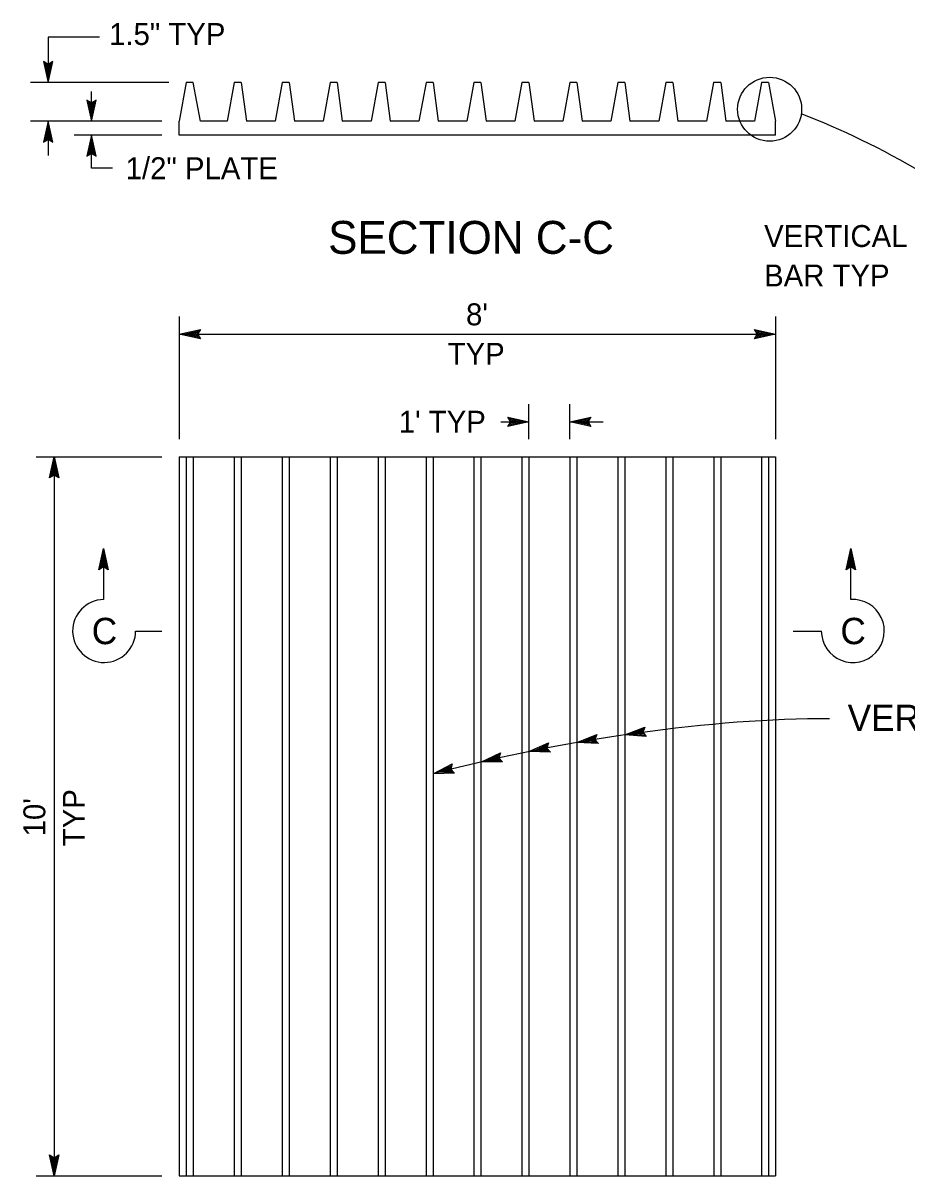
# Model space of a CAD drawing. Extents: x 6709491 to 6710959, y 1869789 to 1870763.
# Drawn here: x 6710131.7 to 6710373.6, y 1870447.9 to 1870763.4 of the extents above; entities that cross this region are included whole.
import ezdxf

# ---------------------------------------------------------------- set-up
doc = ezdxf.new("R2010")
doc.units = 0
for name, color, linetype in [('56 Stg 3 Anno', 7, 'Continuous'), ('57 Undefined', 7, 'Continuous'), ('60 Nongeo Data', 7, 'Continuous')]:
    doc.layers.add(name, color=color, linetype=linetype)

msp = doc.modelspace()

# ---------------------------------------------------------------- linework, layer by layer
at = {"layer": '56 Stg 3 Anno'}
for p, q in [((6710152.62, 1870759.57), (6710138.55, 1870759.57)), ((6710138.55, 1870759.57), (6710138.55, 1870747.15)), ((6710138.55, 1870752.14), (6710137.26, 1870752.91)), ((6710137.26, 1870752.91), (6710137.26, 1870752.91)), ((6710137.26, 1870752.91), (6710138.55, 1870747.15)), ((6710137.6, 1870752.7), (6710138.55, 1870748.47)), ((6710137.95, 1870752.47), (6710138.55, 1870749.8)), ((6710138.28, 1870752.31), (6710138.55, 1870751.13)), ((6710138.55, 1870747.15), (6710139.83, 1870752.91)), ((6710139.83, 1870752.91), (6710138.55, 1870752.14)), ((6710138.55, 1870748.48), (6710139.48, 1870752.68)), ((6710138.55, 1870749.8), (6710139.15, 1870752.51)), ((6710138.55, 1870751.13), (6710138.8, 1870752.29)), ((6710139.83, 1870752.91), (6710139.83, 1870752.91)), ((6710171.55, 1870747.15), (6710133.75, 1870747.15)), ((6710138.55, 1870747.15), (6710138.55, 1870747.15)), ((6710150.43, 1870736.59), (6710150.43, 1870744.71)), ((6710150.43, 1870741.58), (6710149.14, 1870742.35)), ((6710149.14, 1870742.35), (6710149.14, 1870742.35)), ((6710149.14, 1870742.35), (6710150.43, 1870736.59)), ((6710149.48, 1870742.14), (6710150.43, 1870737.91)), ((6710149.83, 1870741.91), (6710150.43, 1870739.24)), ((6710150.16, 1870741.75), (6710150.43, 1870740.57)), ((6710150.43, 1870736.59), (6710151.71, 1870742.35)), ((6710151.71, 1870742.35), (6710150.43, 1870741.58)), ((6710150.43, 1870737.92), (6710151.36, 1870742.12)), ((6710150.43, 1870739.24), (6710151.03, 1870741.95)), ((6710150.43, 1870740.57), (6710150.68, 1870741.73)), ((6710151.71, 1870742.35), (6710151.71, 1870742.35)), ((6710169.63, 1870736.59), (6710133.75, 1870736.59)), ((6710138.55, 1870736.59), (6710137.27, 1870730.83)), ((6710138.55, 1870735.25), (6710137.62, 1870731.05)), ((6710138.55, 1870736.59), (6710138.55, 1870727.21)), ((6710139.84, 1870730.83), (6710138.55, 1870736.59)), ((6710138.55, 1870736.59), (6710138.55, 1870736.59)), ((6710139.49, 1870731.03), (6710138.55, 1870735.26)), ((6710150.43, 1870736.59), (6710150.43, 1870736.59)), ((6710138.55, 1870733.93), (6710137.95, 1870731.22)), ((6710138.55, 1870732.61), (6710138.3, 1870731.45)), ((6710139.15, 1870731.26), (6710138.55, 1870733.93)), ((6710138.82, 1870731.43), (6710138.55, 1870732.61)), ((6710169.63, 1870732.75), (6710145.63, 1870732.75)), ((6710150.43, 1870732.75), (6710149.15, 1870726.99)), ((6710150.43, 1870723.72), (6710150.43, 1870732.75)), ((6710151.72, 1870726.99), (6710150.43, 1870732.75)), ((6710150.43, 1870732.75), (6710150.43, 1870732.75)), ((6710137.27, 1870730.83), (6710138.55, 1870731.59)), ((6710137.27, 1870730.83), (6710137.27, 1870730.83)), ((6710138.55, 1870731.59), (6710139.84, 1870730.83)), ((6710139.84, 1870730.83), (6710139.84, 1870730.83)), ((6710150.43, 1870731.41), (6710149.5, 1870727.21)), ((6710150.43, 1870730.09), (6710149.83, 1870727.38)), ((6710150.43, 1870728.77), (6710150.18, 1870727.61)), ((6710151.37, 1870727.19), (6710150.43, 1870731.42)), ((6710151.03, 1870727.42), (6710150.43, 1870730.09)), ((6710150.7, 1870727.59), (6710150.43, 1870728.77)), ((6710149.15, 1870726.99), (6710150.43, 1870727.75)), ((6710149.15, 1870726.99), (6710149.15, 1870726.99)), ((6710150.43, 1870727.75), (6710151.72, 1870726.99)), ((6710151.72, 1870726.99), (6710151.72, 1870726.99)), ((6710156.16, 1870723.72), (6710150.43, 1870723.72)), ((6710174.43, 1870683.13), (6710174.43, 1870649.53)), ((6710337.63, 1870683.13), (6710337.63, 1870649.53)), ((6710174.43, 1870678.33), (6710180.19, 1870679.61)), ((6710174.43, 1870678.33), (6710180.19, 1870679.61)), ((6710174.43, 1870678.33), (6710337.63, 1870678.33)), ((6710180.19, 1870677.04), (6710174.43, 1870678.33)), ((6710174.43, 1870678.33), (6710174.43, 1870678.33)), ((6710180.19, 1870677.04), (6710174.43, 1870678.33)), ((6710174.43, 1870678.33), (6710174.43, 1870678.33)), ((6710179.98, 1870677.39), (6710175.75, 1870678.33)), ((6710179.98, 1870677.39), (6710175.75, 1870678.33)), ((6710175.77, 1870678.33), (6710179.96, 1870679.26)), ((6710175.77, 1870678.33), (6710179.96, 1870679.26)), ((6710177.08, 1870678.33), (6710179.79, 1870678.93)), ((6710177.08, 1870678.33), (6710179.79, 1870678.93)), ((6710179.76, 1870677.73), (6710177.08, 1870678.33)), ((6710179.76, 1870677.73), (6710177.08, 1870678.33)), ((6710178.41, 1870678.33), (6710179.57, 1870678.59)), ((6710178.41, 1870678.33), (6710179.57, 1870678.59)), ((6710179.59, 1870678.06), (6710178.41, 1870678.33)), ((6710179.59, 1870678.06), (6710178.41, 1870678.33)), ((6710180.19, 1870679.61), (6710179.42, 1870678.33)), ((6710180.19, 1870679.61), (6710179.42, 1870678.33)), ((6710179.42, 1870678.33), (6710180.19, 1870677.04)), ((6710179.42, 1870678.33), (6710180.19, 1870677.04)), ((6710180.19, 1870679.61), (6710180.19, 1870679.61)), ((6710180.19, 1870679.61), (6710180.19, 1870679.61)), ((6710332.64, 1870678.33), (6710331.87, 1870679.62)), ((6710331.87, 1870679.62), (6710331.87, 1870679.62)), ((6710331.87, 1870679.62), (6710337.63, 1870678.33)), ((6710337.63, 1870678.33), (6710331.87, 1870677.05)), ((6710331.87, 1870677.05), (6710332.64, 1870678.33)), ((6710332.08, 1870679.28), (6710336.31, 1870678.33)), ((6710336.3, 1870678.33), (6710332.1, 1870677.4)), ((6710334.98, 1870678.33), (6710332.27, 1870677.73)), ((6710332.31, 1870678.93), (6710334.98, 1870678.33)), ((6710332.48, 1870678.6), (6710333.66, 1870678.33)), ((6710333.66, 1870678.33), (6710332.49, 1870678.08)), ((6710337.63, 1870678.33), (6710337.63, 1870678.33)), ((6710180.19, 1870677.04), (6710180.19, 1870677.04)), ((6710180.19, 1870677.04), (6710180.19, 1870677.04)), ((6710331.87, 1870677.05), (6710331.87, 1870677.05)), ((6710270.11, 1870649.53), (6710270.11, 1870659.14)), ((6710281.31, 1870649.53), (6710281.31, 1870659.14)), ((6710262.46, 1870654.34), (6710270.11, 1870654.34)), ((6710265.12, 1870654.34), (6710264.35, 1870655.62)), ((6710264.35, 1870655.62), (6710264.35, 1870655.62)), ((6710264.35, 1870655.62), (6710270.11, 1870654.34)), ((6710270.11, 1870654.34), (6710264.35, 1870653.06)), ((6710264.35, 1870653.06), (6710265.12, 1870654.34)), ((6710264.35, 1870653.06), (6710264.35, 1870653.06)), ((6710264.56, 1870655.28), (6710268.79, 1870654.34)), ((6710268.78, 1870654.33), (6710264.58, 1870653.41)), ((6710267.46, 1870654.34), (6710264.75, 1870653.74)), ((6710264.79, 1870654.94), (6710267.46, 1870654.34)), ((6710264.96, 1870654.6), (6710266.14, 1870654.34)), ((6710266.14, 1870654.34), (6710264.98, 1870654.08)), ((6710270.11, 1870654.34), (6710270.11, 1870654.34)), ((6710281.31, 1870654.34), (6710287.08, 1870655.62)), ((6710281.31, 1870654.34), (6710290.43, 1870654.34)), ((6710287.08, 1870653.05), (6710281.31, 1870654.34)), ((6710281.31, 1870654.34), (6710281.31, 1870654.34)), ((6710286.87, 1870653.39), (6710282.64, 1870654.34)), ((6710282.65, 1870654.34), (6710286.85, 1870655.27)), ((6710283.97, 1870654.34), (6710286.68, 1870654.94)), ((6710286.64, 1870653.74), (6710283.97, 1870654.34)), ((6710285.29, 1870654.34), (6710286.45, 1870654.59)), ((6710286.47, 1870654.07), (6710285.29, 1870654.34)), ((6710287.08, 1870655.62), (6710286.31, 1870654.34)), ((6710286.31, 1870654.34), (6710287.08, 1870653.05)), ((6710287.08, 1870655.62), (6710287.08, 1870655.62)), ((6710287.08, 1870653.05), (6710287.08, 1870653.05)), ((6710135.3, 1870644.73), (6710169.63, 1870644.73)), ((6710138.88, 1870638.97), (6710140.17, 1870644.73)), ((6710138.88, 1870638.97), (6710140.17, 1870644.73)), ((6710139.22, 1870639.18), (6710140.17, 1870643.41)), ((6710139.22, 1870639.18), (6710140.17, 1870643.41)), ((6710140.17, 1870644.73), (6710140.17, 1870447.93)), ((6710140.17, 1870644.73), (6710140.17, 1870644.73)), ((6710140.17, 1870644.73), (6710141.44, 1870638.97)), ((6710140.17, 1870644.73), (6710140.17, 1870644.73)), ((6710140.17, 1870644.73), (6710141.44, 1870638.97)), ((6710140.17, 1870643.39), (6710141.1, 1870639.2)), ((6710140.17, 1870643.39), (6710141.1, 1870639.2)), ((6710139.57, 1870639.4), (6710140.16, 1870642.08)), ((6710139.57, 1870639.4), (6710140.16, 1870642.08)), ((6710139.9, 1870639.57), (6710140.16, 1870640.75)), ((6710139.9, 1870639.57), (6710140.16, 1870640.75)), ((6710140.16, 1870642.08), (6710140.77, 1870639.37)), ((6710140.16, 1870642.08), (6710140.77, 1870639.37)), ((6710140.16, 1870640.75), (6710140.42, 1870639.59)), ((6710140.16, 1870640.75), (6710140.42, 1870639.59)), ((6710140.17, 1870639.74), (6710138.88, 1870638.97)), ((6710140.17, 1870639.74), (6710138.88, 1870638.97)), ((6710138.88, 1870638.97), (6710138.88, 1870638.97)), ((6710138.88, 1870638.97), (6710138.88, 1870638.97)), ((6710141.44, 1870638.97), (6710140.17, 1870639.74)), ((6710141.44, 1870638.97), (6710140.17, 1870639.74)), ((6710141.44, 1870638.97), (6710141.44, 1870638.97)), ((6710141.44, 1870638.97), (6710141.44, 1870638.97)), ((6710152.41, 1870613.85), (6710153.7, 1870619.62)), ((6710152.75, 1870614.06), (6710153.7, 1870618.29)), ((6710153.7, 1870619.62), (6710153.7, 1870619.62)), ((6710153.7, 1870619.62), (6710154.98, 1870613.85)), ((6710153.7, 1870619.62), (6710153.7, 1870605.68)), ((6710153.7, 1870618.28), (6710154.63, 1870614.08)), ((6710356.94, 1870613.85), (6710358.23, 1870619.62)), ((6710357.28, 1870614.06), (6710358.23, 1870618.29)), ((6710358.23, 1870619.62), (6710358.23, 1870619.62)), ((6710358.23, 1870619.62), (6710359.51, 1870613.85)), ((6710358.23, 1870605.68), (6710358.23, 1870619.62)), ((6710358.23, 1870618.28), (6710359.16, 1870614.08)), ((6710153.1, 1870614.28), (6710153.7, 1870616.96)), ((6710153.43, 1870614.45), (6710153.7, 1870615.63)), ((6710153.7, 1870616.96), (6710154.3, 1870614.25)), ((6710153.7, 1870615.63), (6710153.95, 1870614.47)), ((6710357.63, 1870614.28), (6710358.23, 1870616.96)), ((6710357.96, 1870614.45), (6710358.23, 1870615.63)), ((6710358.23, 1870616.96), (6710358.83, 1870614.25)), ((6710358.23, 1870615.63), (6710358.48, 1870614.47)), ((6710153.7, 1870614.62), (6710152.41, 1870613.85)), ((6710152.41, 1870613.85), (6710152.41, 1870613.85)), ((6710154.98, 1870613.85), (6710153.7, 1870614.62)), ((6710154.98, 1870613.85), (6710154.98, 1870613.85)), ((6710358.23, 1870614.62), (6710356.94, 1870613.85)), ((6710356.94, 1870613.85), (6710356.94, 1870613.85)), ((6710359.51, 1870613.85), (6710358.23, 1870614.62)), ((6710359.51, 1870613.85), (6710359.51, 1870613.85)), ((6710162.49, 1870597.06), (6710169.63, 1870597.06)), ((6710342.43, 1870597.06), (6710350.17, 1870597.06)), ((6710296.36, 1870568.62), (6710301.87, 1870570.72)), ((6710301.87, 1870570.72), (6710301.29, 1870569.34)), ((6710301.87, 1870570.72), (6710301.87, 1870570.72)), ((6710283.23, 1870566.52), (6710288.69, 1870568.76)), ((6710284.55, 1870566.75), (6710288.53, 1870568.38)), ((6710285.85, 1870566.97), (6710288.42, 1870568.03)), ((6710287.15, 1870567.19), (6710288.25, 1870567.65)), ((6710288.69, 1870568.76), (6710288.15, 1870567.37)), ((6710288.69, 1870568.76), (6710288.69, 1870568.76)), ((6710302.24, 1870568.18), (6710296.36, 1870568.62)), ((6710296.36, 1870568.62), (6710296.36, 1870568.62)), ((6710301.99, 1870568.49), (6710297.67, 1870568.81)), ((6710297.68, 1870568.82), (6710301.7, 1870570.34)), ((6710298.98, 1870569), (6710301.58, 1870569.99)), ((6710301.71, 1870568.8), (6710298.98, 1870569)), ((6710300.29, 1870569.19), (6710301.4, 1870569.62)), ((6710301.5, 1870569.1), (6710300.29, 1870569.19)), ((6710301.29, 1870569.34), (6710302.24, 1870568.18)), ((6710302.24, 1870568.18), (6710302.24, 1870568.18)), ((6710270.11, 1870564.05), (6710275.51, 1870566.44)), ((6710271.42, 1870564.31), (6710275.35, 1870566.06)), ((6710272.71, 1870564.57), (6710275.25, 1870565.7)), ((6710275.46, 1870564.51), (6710272.71, 1870564.57)), ((6710274.01, 1870564.83), (6710275.1, 1870565.31)), ((6710275.22, 1870564.81), (6710274.01, 1870564.83)), ((6710275.51, 1870566.44), (6710275.01, 1870565.04)), ((6710275.01, 1870565.04), (6710276.02, 1870563.93)), ((6710275.51, 1870566.44), (6710275.51, 1870566.44)), ((6710289.13, 1870566.24), (6710283.23, 1870566.52)), ((6710283.23, 1870566.52), (6710283.23, 1870566.52)), ((6710288.87, 1870566.54), (6710284.54, 1870566.74)), ((6710288.59, 1870566.84), (6710285.85, 1870566.97)), ((6710288.36, 1870567.14), (6710287.15, 1870567.19)), ((6710288.15, 1870567.37), (6710289.13, 1870566.24)), ((6710289.13, 1870566.24), (6710289.13, 1870566.24)), ((6710256.99, 1870561.21), (6710262.32, 1870563.75)), ((6710262.9, 1870561.25), (6710256.99, 1870561.21)), ((6710262.62, 1870561.54), (6710258.28, 1870561.5)), ((6710258.29, 1870561.51), (6710262.18, 1870563.36)), ((6710259.58, 1870561.8), (6710262.09, 1870563)), ((6710262.32, 1870561.82), (6710259.58, 1870561.8)), ((6710260.87, 1870562.1), (6710261.94, 1870562.61)), ((6710262.08, 1870562.11), (6710260.87, 1870562.1)), ((6710262.32, 1870563.75), (6710261.86, 1870562.33)), ((6710261.86, 1870562.33), (6710262.9, 1870561.25)), ((6710262.32, 1870563.75), (6710262.32, 1870563.75)), ((6710262.9, 1870561.25), (6710262.9, 1870561.25)), ((6710276.02, 1870563.93), (6710270.11, 1870564.05)), ((6710270.11, 1870564.05), (6710270.11, 1870564.05)), ((6710275.74, 1870564.22), (6710271.41, 1870564.31)), ((6710276.02, 1870563.93), (6710276.02, 1870563.93)), ((6710243.87, 1870557.97), (6710249.12, 1870560.67)), ((6710249.77, 1870558.19), (6710243.87, 1870557.97)), ((6710249.48, 1870558.47), (6710245.15, 1870558.31)), ((6710245.16, 1870558.31), (6710248.99, 1870560.28)), ((6710246.44, 1870558.64), (6710248.91, 1870559.91)), ((6710249.18, 1870558.74), (6710246.44, 1870558.64)), ((6710247.72, 1870558.98), (6710248.78, 1870559.52)), ((6710248.93, 1870559.02), (6710247.72, 1870558.98)), ((6710249.12, 1870560.67), (6710248.7, 1870559.24)), ((6710248.7, 1870559.24), (6710249.77, 1870558.19)), ((6710249.12, 1870560.67), (6710249.12, 1870560.67)), ((6710249.77, 1870558.19), (6710249.77, 1870558.19)), ((6710256.99, 1870561.21), (6710256.99, 1870561.21)), ((6710243.87, 1870557.97), (6710243.87, 1870557.97)), ((6710140.17, 1870447.93), (6710138.89, 1870453.69)), ((6710138.89, 1870453.69), (6710138.89, 1870453.69)), ((6710138.89, 1870453.69), (6710140.17, 1870452.92)), ((6710140.16, 1870449.26), (6710139.23, 1870453.46)), ((6710140.17, 1870450.58), (6710139.57, 1870453.29)), ((6710140.17, 1870451.9), (6710139.91, 1870453.06)), ((6710140.17, 1870452.92), (6710141.45, 1870453.69)), ((6710141.45, 1870453.69), (6710140.17, 1870447.93)), ((6710141.11, 1870453.48), (6710140.17, 1870449.25)), ((6710140.77, 1870453.25), (6710140.17, 1870450.58)), ((6710140.43, 1870453.08), (6710140.17, 1870451.9)), ((6710141.45, 1870453.69), (6710141.45, 1870453.69)), ((6710135.3, 1870447.93), (6710169.63, 1870447.93)), ((6710140.17, 1870447.93), (6710140.17, 1870447.93))]:
    msp.add_line(p, q, dxfattribs=at)
msp.add_circle((6710335.99, 1870739.86), 8.76, dxfattribs=at)
for centre, start, end in [((6710153.87, 1870597.07), 91.113, 359.9585), ((6710358.75, 1870597.07), 180.1055, 93.4975)]:
    msp.add_arc(centre, 8.62, start, end, dxfattribs=at)
for centre, major_axis, ratio, start_param, end_param in [((6710372.53, 1870658.15), (96.99, -77), 0.452596, 1.538094, 2.189581), ((6710284.5, 1870536.38), (-119.88, -21.93), 0.24528, 4.066196, 5.012915)]:
    msp.add_ellipse(centre, major_axis=major_axis, ratio=ratio, start_param=start_param, end_param=end_param, dxfattribs=at)
at = {"layer": '60 Nongeo Data'}
for p, q in [((6710176.35, 1870747.15), (6710174.43, 1870736.59)), ((6710178.27, 1870747.15), (6710176.35, 1870747.15)), ((6710180.19, 1870736.59), (6710178.27, 1870747.15)), ((6710189.47, 1870747.15), (6710187.55, 1870736.59)), ((6710191.39, 1870747.15), (6710189.47, 1870747.15)), ((6710191.39, 1870747.15), (6710192.79, 1870736.59)), ((6710202.59, 1870747.15), (6710200.67, 1870736.59)), ((6710204.51, 1870747.15), (6710202.59, 1870747.15)), ((6710204.51, 1870747.15), (6710205.92, 1870736.59)), ((6710215.71, 1870747.15), (6710213.79, 1870736.59)), ((6710217.63, 1870747.15), (6710215.71, 1870747.15)), ((6710217.63, 1870747.15), (6710219.04, 1870736.59)), ((6710228.83, 1870747.15), (6710226.91, 1870736.59)), ((6710230.75, 1870747.15), (6710228.83, 1870747.15)), ((6710230.75, 1870747.15), (6710232.16, 1870736.59)), ((6710241.95, 1870747.15), (6710240.03, 1870736.59)), ((6710243.87, 1870747.15), (6710241.95, 1870747.15)), ((6710243.87, 1870747.15), (6710245.28, 1870736.59)), ((6710255.07, 1870747.15), (6710253.15, 1870736.59)), ((6710256.99, 1870747.15), (6710255.07, 1870747.15)), ((6710256.99, 1870747.15), (6710258.4, 1870736.59)), ((6710268.19, 1870747.15), (6710266.27, 1870736.59)), ((6710270.11, 1870747.15), (6710268.19, 1870747.15)), ((6710270.11, 1870747.15), (6710271.52, 1870736.59)), ((6710281.31, 1870747.15), (6710279.39, 1870736.59)), ((6710283.23, 1870747.15), (6710281.31, 1870747.15)), ((6710283.23, 1870747.15), (6710284.64, 1870736.59)), ((6710294.43, 1870747.15), (6710292.51, 1870736.59)), ((6710296.35, 1870747.15), (6710294.43, 1870747.15)), ((6710296.35, 1870747.15), (6710297.76, 1870736.59)), ((6710307.55, 1870747.15), (6710305.63, 1870736.59)), ((6710309.47, 1870747.15), (6710307.55, 1870747.15)), ((6710309.47, 1870747.15), (6710310.88, 1870736.59)), ((6710320.67, 1870747.15), (6710318.75, 1870736.59)), ((6710322.59, 1870747.15), (6710320.67, 1870747.15)), ((6710322.59, 1870747.15), (6710324, 1870736.59)), ((6710333.79, 1870747.15), (6710331.87, 1870736.59)), ((6710335.71, 1870747.15), (6710333.79, 1870747.15)), ((6710335.71, 1870747.15), (6710337.63, 1870736.59)), ((6710174.43, 1870732.75), (6710174.43, 1870736.59)), ((6710187.55, 1870736.59), (6710180.19, 1870736.59)), ((6710200.67, 1870736.59), (6710192.79, 1870736.59)), ((6710213.79, 1870736.59), (6710205.92, 1870736.59)), ((6710226.91, 1870736.59), (6710219.04, 1870736.59)), ((6710240.03, 1870736.59), (6710232.16, 1870736.59)), ((6710253.15, 1870736.59), (6710245.28, 1870736.59)), ((6710266.27, 1870736.59), (6710258.4, 1870736.59)), ((6710279.39, 1870736.59), (6710271.52, 1870736.59)), ((6710292.51, 1870736.59), (6710284.64, 1870736.59)), ((6710305.63, 1870736.59), (6710297.76, 1870736.59)), ((6710318.75, 1870736.59), (6710310.88, 1870736.59)), ((6710331.87, 1870736.59), (6710324, 1870736.59)), ((6710337.63, 1870732.75), (6710337.63, 1870736.59)), ((6710337.63, 1870732.75), (6710174.43, 1870732.75)), ((6710174.43, 1870644.73), (6710337.63, 1870644.73)), ((6710174.43, 1870644.73), (6710174.43, 1870447.93)), ((6710176.35, 1870644.73), (6710176.35, 1870447.93)), ((6710178.27, 1870644.73), (6710178.27, 1870447.93)), ((6710189.47, 1870644.73), (6710189.47, 1870447.93)), ((6710191.39, 1870644.73), (6710191.39, 1870447.93)), ((6710202.59, 1870644.73), (6710202.59, 1870447.93)), ((6710204.51, 1870644.73), (6710204.51, 1870447.93)), ((6710215.71, 1870644.73), (6710215.71, 1870447.93)), ((6710217.63, 1870644.73), (6710217.63, 1870447.93)), ((6710228.83, 1870644.73), (6710228.83, 1870447.93)), ((6710230.75, 1870644.73), (6710230.75, 1870447.93)), ((6710241.95, 1870644.73), (6710241.95, 1870447.93)), ((6710243.87, 1870644.73), (6710243.87, 1870447.93)), ((6710255.07, 1870644.73), (6710255.07, 1870447.93)), ((6710256.99, 1870644.73), (6710256.99, 1870447.93)), ((6710268.19, 1870644.73), (6710268.19, 1870447.93)), ((6710270.11, 1870644.73), (6710270.11, 1870447.93)), ((6710281.31, 1870644.73), (6710281.31, 1870447.93)), ((6710283.23, 1870644.73), (6710283.23, 1870447.93)), ((6710294.44, 1870644.73), (6710294.44, 1870447.93)), ((6710296.36, 1870644.73), (6710296.36, 1870447.93)), ((6710307.56, 1870644.73), (6710307.56, 1870447.93)), ((6710309.48, 1870644.73), (6710309.48, 1870447.93)), ((6710320.68, 1870644.73), (6710320.68, 1870447.93)), ((6710322.6, 1870644.73), (6710322.6, 1870447.93)), ((6710333.79, 1870644.73), (6710333.79, 1870447.93)), ((6710335.71, 1870644.73), (6710335.71, 1870447.93)), ((6710337.63, 1870644.73), (6710337.63, 1870447.93)), ((6710174.43, 1870447.93), (6710337.63, 1870447.93))]:
    msp.add_line(p, q, dxfattribs=at)

# ---------------------------------------------------------------- texts
at = {"layer": '57 Undefined'}
for s, height, p in [('1.5" TYP', 6, (6710155.22, 1870757.45)), ('1/2" PLATE', 6, (6710159.75, 1870720.72)), ('SECTION C-C', 9, (6710215.16, 1870700.29)), ('VERTICAL', 6, (6710334.48, 1870702.16)), ('BAR TYP', 6, (6710334.48, 1870691.36)), ("8'", 6, (6710252.9, 1870680.73)), ('TYP', 6, (6710247.88, 1870669.93)), ("1' TYP", 6, (6710234.49, 1870651.34)), ('C', 7.21, (6710150.47, 1870593.46)), ('C', 7.21, (6710355.36, 1870593.46)), ('VERTICAL BARS', 7.2002, (6710357.34, 1870569.69))]:
    msp.add_text(s, height=height, dxfattribs=at).set_placement(p)
for s, p in [('TYP', (6710148.57, 1870538.17)), ("10'", (6710137.77, 1870540.87))]:
    msp.add_text(s, height=6, rotation=90, dxfattribs=at).set_placement(p)

doc.saveas('drawing.dxf')
